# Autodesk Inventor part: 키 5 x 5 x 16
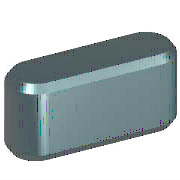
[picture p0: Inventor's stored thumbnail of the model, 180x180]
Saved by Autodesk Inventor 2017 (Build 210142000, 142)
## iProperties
IsCustomPart: 1
Created: 2012-02
Part Number: 키 5 x 5 x 16
Material: 강철, 연강
Description: 키 및 해당 키홈
Document SubType Name: Modeling
Standard: KS B 1311
Designer: mduedu
Standards Organization: KS
Language: ko-KR
Size Designation: 5 x 5 x 16
Categories: <MemberInstance><Categories><Category DisplayName="샤프트 부품" InternalName="7f7aeb1f-a693-4053-b835-cee3144e0d98" Mnemonic="SHFT"><Category DisplayName="키" Interna
Density: 1 g/cm^3
Appearance: 노란색
Author: mduedu
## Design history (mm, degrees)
workplane "Work Plane1"
workplane "Work Plane2"
sketch "스케치1"
  geometry: L1 (2.5, 2.5)-(13.5, 2.5); L2 (13.5, -2.5)-(2.5, -2.5); L3 (0, 9.4)-(0, -7.4) reference; L4 (-5, 0)-(30, 0) reference; L5 (16, 0)-(16, 7); A1 r 2.5 centre (2.5, 0) between (2.5, 2.5) and (2.5, -2.5); A2 r 2.5 centre (13.5, 0) between (13.5, -2.5) and (13.5, 2.5)
  constraints: 6 end point, 5 point on circle, 4 tangent, 3 point on line, 2 centre point, 1 horizontal, 1 parallel, 1 perpendicular
  dimensions: "d0" = 2.5 radius of A1 (= 0.5 x PB); "d13" = 2.5 radius of A2 (= 0.5 x PB); "d14" = 16 distance between parallel lines of L5 L3 (= NLG)
extrude "본체1" new body sketch "스케치1" taper "d3" = 0 deg; stored distance "d4" = 10
workplane "Work Plane3"
body "Solid1"
chamfer "모따기1" distance "d8" = 0.4 (= PHH); stored, may be unused: second distance "d9" = 0.4 (= PHH), angle "d15" = 45 deg
other parameters: "d1" = -3 (= -PNT), "d2" = 2 (= PH - PNT), "NLG" = 16 [user parameter; used in 3 equation terms], "PB" = 5 [user parameter; used in 2 equation terms], "PNT" = 3 [user parameter; used in 2 equation terms], "PH" = 5 [user parameter; used in 1 equation term], "PHH" = 0.4 [user parameter; used in 2 equation terms], "d10" = 0, "d16" = 0, "d17" = 0, "d18" = 0, "WDMIN" = 12 [user parameter], "PLB2" = 16 (= NLG) [user parameter], "WDMAX" = 17 [user parameter], "PLB1" = 16 (= NLG) [user parameter], "RR" = 0.16 [user parameter], "PUEB" = 2.3 [user parameter]
